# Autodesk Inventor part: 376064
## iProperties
Company: Mayer & Müller AG Schaltgeräte
Created: 2005-06
Part Number: 376064
Material: Gummi
Document SubType Name: Modeling
Designer: I.Baliuc
Manufacturer: Standard
Standards Organization: Custom
Description: O-Ring
Density: 0.93 g/cm^3
Author: T.Messerschmitt
Revision Number: 376064
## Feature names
1. Drehung1 [Revolution]
